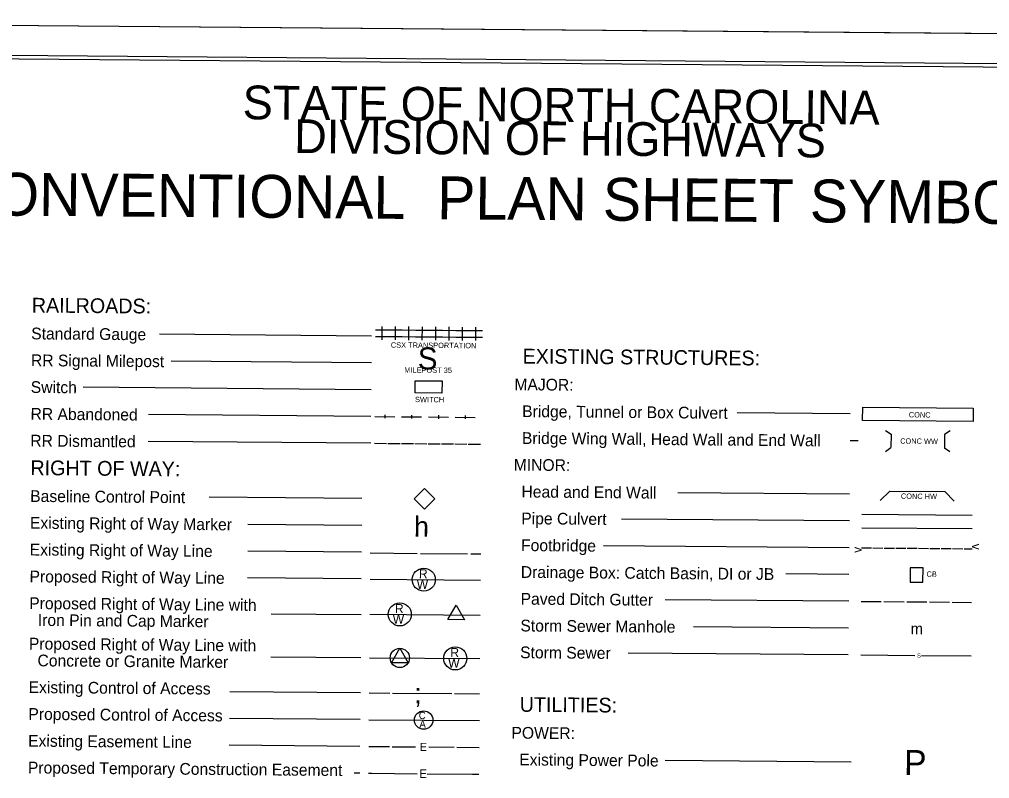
# Model space of a CAD drawing. Extents: x 1379453 to 1387082, y 594364 to 596664.
# Drawn here: x 1384828 to 1386277, y 595530 to 596664 of the extents above; entities that cross this region are included whole.
import ezdxf

# ---------------------------------------------------------------- set-up
doc = ezdxf.new("R2010")
doc.units = 0
for name, color, linetype in [('Default', 7, 'Continuous'), ('Sheet Cutting Line CELL', 7, 'Continuous'), ('Sheet Plot Border Inside CELL', 7, 'Continuous'), ('Sheet Plot Border Outside CELL', 7, 'Continuous'), ('Sheet Symbology CELL', 7, 'Continuous')]:
    doc.layers.add(name, color=color, linetype=linetype)

msp = doc.modelspace()

# ---------------------------------------------------------------- linework, layer by layer
at = {"layer": 'Default'}
msp.add_lwpolyline([(1385417.6, 595948.2), (1385433.4, 595963.7), (1385448.9, 595947.9), (1385433.1, 595932.4)], close=True, dxfattribs=at)
at = {"layer": 'Sheet Cutting Line CELL'}
msp.add_line((1387081.8, 596635.6), (1383713.9, 596663.8), dxfattribs=at)
at = {"layer": 'Sheet Plot Border Inside CELL'}
msp.add_lwpolyline([(1383721.8, 594508.6), (1387054.7, 594480.6), (1387072.4, 596590.8), (1383739.5, 596618.7)], close=True, dxfattribs=at)
at = {"layer": 'Sheet Plot Border Outside CELL'}
msp.add_lwpolyline([(1383695.4, 594463.9), (1387063.3, 594435.7), (1387081.8, 596635.6), (1383713.9, 596663.8)], close=True, dxfattribs=at)
at = {"layer": 'Sheet Symbology CELL'}
for p, q in [((1385360.1, 596200.5), (1385380.1, 596200.3)), ((1385370, 596185.4), (1385370.1, 596205.4)), ((1385380.1, 596200.3), (1385400.1, 596200.2)), ((1385390, 596185.3), (1385390.1, 596205.3)), ((1385400.1, 596200.2), (1385420.1, 596200)), ((1385410, 596185.1), (1385410.1, 596205.1)), ((1385420.1, 596200), (1385440.1, 596199.8)), ((1385430, 596184.9), (1385430.1, 596204.9)), ((1385440.1, 596199.8), (1385460.1, 596199.7)), ((1385450, 596184.8), (1385450.1, 596204.8)), ((1385460.1, 596199.7), (1385480.1, 596199.5)), ((1385470, 596184.6), (1385470.1, 596204.6)), ((1385480.1, 596199.5), (1385500.1, 596199.3)), ((1385490, 596184.4), (1385490.1, 596204.4)), ((1385500.1, 596199.3), (1385520.1, 596199.2)), ((1385509.9, 596184.2), (1385510.1, 596204.2)), ((1385354.3, 596191), (1385037.4, 596193.7)), ((1385360, 596190.5), (1385380, 596190.3)), ((1385380, 596190.3), (1385400, 596190.2)), ((1385400, 596190.2), (1385420, 596190)), ((1385420, 596190), (1385440, 596189.8)), ((1385440, 596189.8), (1385460, 596189.7)), ((1385460, 596189.7), (1385480, 596189.5)), ((1385480, 596189.5), (1385500, 596189.3)), ((1385500, 596189.3), (1385520, 596189.2)), ((1385353.9, 596151), (1385054.8, 596153.5)), ((1385353.6, 596111), (1384923.8, 596114.6)), ((1385353.2, 596071), (1385020.9, 596073.8)), ((1385359, 596071), (1385389, 596070.7)), ((1385374, 596073.4), (1385374, 596068.4)), ((1385399, 596070.6), (1385429, 596070.4)), ((1385414, 596073), (1385414, 596068)), ((1385439, 596070.3), (1385469, 596070.1)), ((1385454, 596072.7), (1385454, 596067.7)), ((1385479, 596070), (1385509, 596069.7)), ((1385494, 596072.4), (1385494, 596067.4)), ((1386069, 596075.1), (1385900.2, 596076.5)), ((1386121.7, 596050.3), (1386129.9, 596044.6)), ((1386129.9, 596044.6), (1386129.7, 596024.6)), ((1386209.8, 596043.9), (1386209.7, 596023.9)), ((1386218.1, 596049.5), (1386209.8, 596043.9)), ((1385352.9, 596031), (1385020.6, 596033.8)), ((1385352.9, 596031), (1385020.6, 596033.8)), ((1385358.7, 596031), (1385376.7, 596030.8)), ((1385378.7, 596030.8), (1385396.7, 596030.7)), ((1385398.7, 596030.7), (1385416.7, 596030.5)), ((1385418.7, 596030.5), (1385436.7, 596030.3)), ((1385438.7, 596030.3), (1385456.7, 596030.2)), ((1385458.7, 596030.1), (1385476.7, 596030)), ((1385478.7, 596030), (1385496.7, 596029.8)), ((1385498.7, 596029.8), (1385516.7, 596029.7)), ((1386068.7, 596035.1), (1386080.6, 596035)), ((1386121.4, 596018.9), (1386129.7, 596024.6)), ((1386217.8, 596018.1), (1386209.7, 596023.9)), ((1386068, 595955.1), (1385811.4, 595957.2)), ((1386113.6, 595945.5), (1386127.9, 595959.6)), ((1386127.9, 595959.6), (1386210.4, 595958.9)), ((1386210.4, 595958.9), (1386224.4, 595944.6)), ((1385339.9, 595948.4), (1385111.5, 595950.4)), ((1386086.3, 595924.9), (1386251.3, 595923.5)), ((1385339.6, 595908.4), (1385169.7, 595909.9)), ((1386067.7, 595915.1), (1385727.3, 595917.9)), ((1386086.2, 595904.9), (1386251.2, 595903.5)), ((1385339.3, 595868.4), (1385169.4, 595869.9)), ((1385352.3, 595867.2), (1385422.3, 595866.6)), ((1385427.3, 595866.6), (1385497.3, 595866)), ((1385502.3, 595865.9), (1385517.3, 595865.8)), ((1386067.3, 595875.1), (1385700.4, 595878.1)), ((1386085.9, 595874.9), (1386100.9, 595874.8)), ((1386102.9, 595874.8), (1386117.9, 595874.6)), ((1386119.9, 595874.6), (1386134.9, 595874.5)), ((1386136.9, 595874.5), (1386151.9, 595874.4)), ((1386153.9, 595874.3), (1386168.9, 595874.2)), ((1386170.9, 595874.2), (1386185.9, 595874.1)), ((1386187.9, 595874.1), (1386202.9, 595873.9)), ((1386204.9, 595873.9), (1386219.9, 595873.8)), ((1386221.9, 595873.8), (1386236.9, 595873.6)), ((1386238.9, 595873.6), (1386250.9, 595873.5)), ((1386067, 595835.1), (1385972.6, 595835.9)), ((1385338.9, 595828.4), (1385169.1, 595829.9)), ((1385352, 595828.1), (1385517, 595826.7)), ((1386066.7, 595795.1), (1385792.8, 595797.4)), ((1386085.3, 595794.9), (1386115.3, 595794.7)), ((1386119.3, 595794.6), (1386149.3, 595794.4)), ((1386153.3, 595794.3), (1386183.3, 595794.1)), ((1386187.3, 595794.1), (1386217.3, 595793.8)), ((1386221.3, 595793.8), (1386250.3, 595793.5)), ((1385338.5, 595774.7), (1385204.3, 595775.9)), ((1385351.5, 595775.8), (1385516.5, 595774.5)), ((1385480.4, 595774.8), (1385480.4, 595774.8)), ((1386066.3, 595755.1), (1385835, 595757)), ((1385338, 595710.7), (1385203.7, 595711.8)), ((1385351, 595710.8), (1385516, 595709.5)), ((1385396.4, 595710.5), (1385396.4, 595710.5)), ((1386066, 595715.1), (1385737.6, 595717.8)), ((1386084.6, 595714.9), (1386165.6, 595714.2)), ((1386175.6, 595714.2), (1386249.6, 595713.5)), ((1385337.5, 595658.4), (1385142.4, 595660.1)), ((1385350.5, 595658.3), (1385381.5, 595658.1)), ((1385385.5, 595658), (1385474.3, 595657.3)), ((1385478.3, 595657.3), (1385515.5, 595657)), ((1385337.2, 595618.5), (1385142.1, 595620.1)), ((1385350.2, 595618.3), (1385515.2, 595617)), ((1385336.8, 595578.5), (1385141.8, 595580.1)), ((1385349.9, 595578.3), (1385380.9, 595578.1)), ((1385384.9, 595578), (1385419.9, 595577.8)), ((1385439.9, 595577.6), (1385477.4, 595577.3)), ((1385481.4, 595577.2), (1385514.9, 595577)), ((1386070.2, 595555), (1385792.8, 595557.4)), ((1385336.5, 595538.5), (1385328.2, 595538.5)), ((1385349.5, 595538.3), (1385354.8, 595538.3)), ((1385354.8, 595538.3), (1385422.3, 595537.7)), ((1385437.3, 595537.6), (1385504.8, 595537)), ((1385504.8, 595537), (1385514.5, 595537))]:
    msp.add_line(p, q, dxfattribs=at)
for points in [[(1387047.3, 596585.9), (1384047.4, 596611), (1384029.9, 594511.1), (1387029.8, 594486)], [(1385419.4, 596124.4), (1385459.4, 596124.1), (1385459.3, 596105.9), (1385419.3, 596106.2)], [(1386158.4, 595823.7), (1386177.6, 595823.5), (1386177.8, 595844.8), (1386158.6, 595845)], [(1385467.9, 595767.7), (1385480.5, 595789.2), (1385492.9, 595767.5)], [(1385383.8, 595703.4), (1385396.5, 595724.9), (1385408.8, 595703.2)]]:
    msp.add_lwpolyline(points, close=True, dxfattribs=at)
msp.add_lwpolyline([(1386087.7, 596084.9), (1386252.7, 596083.5), (1386252.5, 596063.5), (1386087.5, 596064.9), (1386087.7, 596084.9)], dxfattribs=at)
for centre, radius in [((1385432.2, 595827.4), 17.2), ((1385396.4, 595775.5), 17.2), ((1385396.4, 595710.5), 14.4), ((1385479.2, 595709.8), 17.2), ((1385432, 595617.7), 13.8)]:
    msp.add_circle(centre, radius, dxfattribs=at)

# ---------------------------------------------------------------- texts
for s, height, rotation, p in [('STATE OF NORTH CAROLINA', 50.398, 359.52, (1385161.6, 596514.8)), ('DIVISION OF HIGHWAYS', 50.398, 359.52, (1385238.5, 596464.3)), ('CONVENTIONAL  PLAN SHEET SYMBOLS', 64.001, 359.52, (1384729.2, 596371.6)), ('RAILROADS:', 22, 359.52, (1384846.8, 596226.2)), ('Standard Gauge', 17.5, 359.52, (1384845.9, 596186.2)), ('CSX TRANSPORTATION', 8, 359.52, (1385383, 596173.8)), ('S', 33, 359.52, (1385423.1, 596141.2)), ('EXISTING STRUCTURES:', 22, 359.52, (1385579.7, 596150.1)), ('RR Signal Milepost', 17.5, 359.52, (1384845.5, 596146.2)), ('MILEPOST 35', 8, 359.52, (1385403, 596136.5)), ('MAJOR:', 17.5, 359.52, (1385567.4, 596110.2)), ('Switch', 17.5, 359.52, (1384845.2, 596106.2)), ('SWITCH', 8, 359.52, (1385419.1, 596092.4)), ('RR Abandoned', 17.5, 359.52, (1384844.9, 596066.2)), ('Bridge, Tunnel or Box Culvert', 17.5, 359.52, (1385579, 596070.1)), ('CONC', 8, 359.52, (1386156.4, 596069.6)), ('RR Dismantled', 17.5, 359.52, (1384844.5, 596026.2)), ('Bridge Wing Wall, Head Wall and End Wall', 17.5, 359.52, (1385578.7, 596030.1)), ('CONC WW', 8, 359.52, (1386143.5, 596030.4)), ('RIGHT OF WAY:', 22, 359.52, (1384844.7, 595983.5)), ('MINOR:', 17.5, 359.52, (1385566.4, 595990.2)), ('Head and End Wall', 17.5, 359.52, (1385578, 595950.1)), ('Baseline Control Point', 17.5, 359.52, (1384844.4, 595943.5)), ('CONC HW', 8, 359.52, (1386144.6, 595948.1)), ('h', 30, 359.52, (1385417.5, 595891.6)), ('Pipe Culvert', 17.5, 359.52, (1385577.7, 595910.1)), ('Existing Right of Way Marker', 17.5, 359.52, (1384844, 595903.5)), ('Existing Right of Way Line', 17.5, 359.52, (1384843.7, 595863.5)), ('Footbridge', 17.5, 359.52, (1385577.4, 595870.1)), ('v', 13.2, 269.7609, (1386251, 595881)), ('v', 13.2, 89.2792, (1386085.8, 595867.4)), ('Proposed Right of Way Line', 17.5, 359.52, (1384843.4, 595823.5)), ('R', 13.5, 359.52, (1385424.8, 595829.5)), ('Drainage Box: Catch Basin, DI or JB', 17.5, 359.52, (1385577, 595830.1)), ('CB', 8, 359.52, (1386182.9, 595831.7)), ('W', 13.5, 359.52, (1385421.6, 595813.6)), ('Paved Ditch Gutter', 17.5, 359.52, (1385576.7, 595790.1)), ('Proposed Right of Way Line with', 17.5, 359.52, (1384843, 595783.5)), ('R', 13.5, 359.52, (1385389, 595777.5)), ('  Iron Pin and Cap Marker', 17.5, 359.52, (1384842.8, 595758.5)), ('W', 13.5, 359.52, (1385385.8, 595761.7)), ('Storm Sewer Manhole', 17.5, 359.52, (1385576.4, 595750.1)), ('m', 16.5, 359.52, (1386159.1, 595746)), ('Proposed Right of Way Line with', 17.5, 359.52, (1384842.5, 595723.1)), ('R', 13.5, 359.52, (1385471.8, 595711.9)), ('Storm Sewer', 17.5, 359.52, (1385576, 595710.1)), ('  Concrete or Granite Marker', 17.5, 359.52, (1384842.3, 595698.1)), ('W', 13.5, 359.52, (1385468.6, 595696)), ('S', 6, 359.52, (1386168.8, 595711.2)), ('Existing Control of Access', 17.5, 359.52, (1384842, 595658.1)), (';', 30, 359.52, (1385417.9, 595642.8)), ('UTILITIES:', 22, 359.52, (1385575.3, 595630.1)), ('Proposed Control of Access', 17.5, 359.52, (1384841.7, 595618.1)), ('C', 10.8, 359.52, (1385424.6, 595619.3)), ('A', 10.8, 359.52, (1385425.6, 595606.4)), ('POWER:', 17.5, 359.52, (1385563, 595590.1)), ('Existing Easement Line', 17.5, 359.52, (1384841.3, 595578.1)), ('E', 12, 359.52, (1385426.2, 595571.7)), ('Existing Power Pole', 17.5, 359.52, (1385574.7, 595550.1)), ('P', 37.5, 359.52, (1386149.3, 595535.6)), ('Proposed Temporary Construction Easement', 17.5, 359.52, (1384841, 595538.1)), ('E', 13.1, 359.52, (1385425.4, 595531.1))]:
    msp.add_text(s, height=height, rotation=rotation, dxfattribs=at).set_placement(p)

doc.saveas('drawing.dxf')
